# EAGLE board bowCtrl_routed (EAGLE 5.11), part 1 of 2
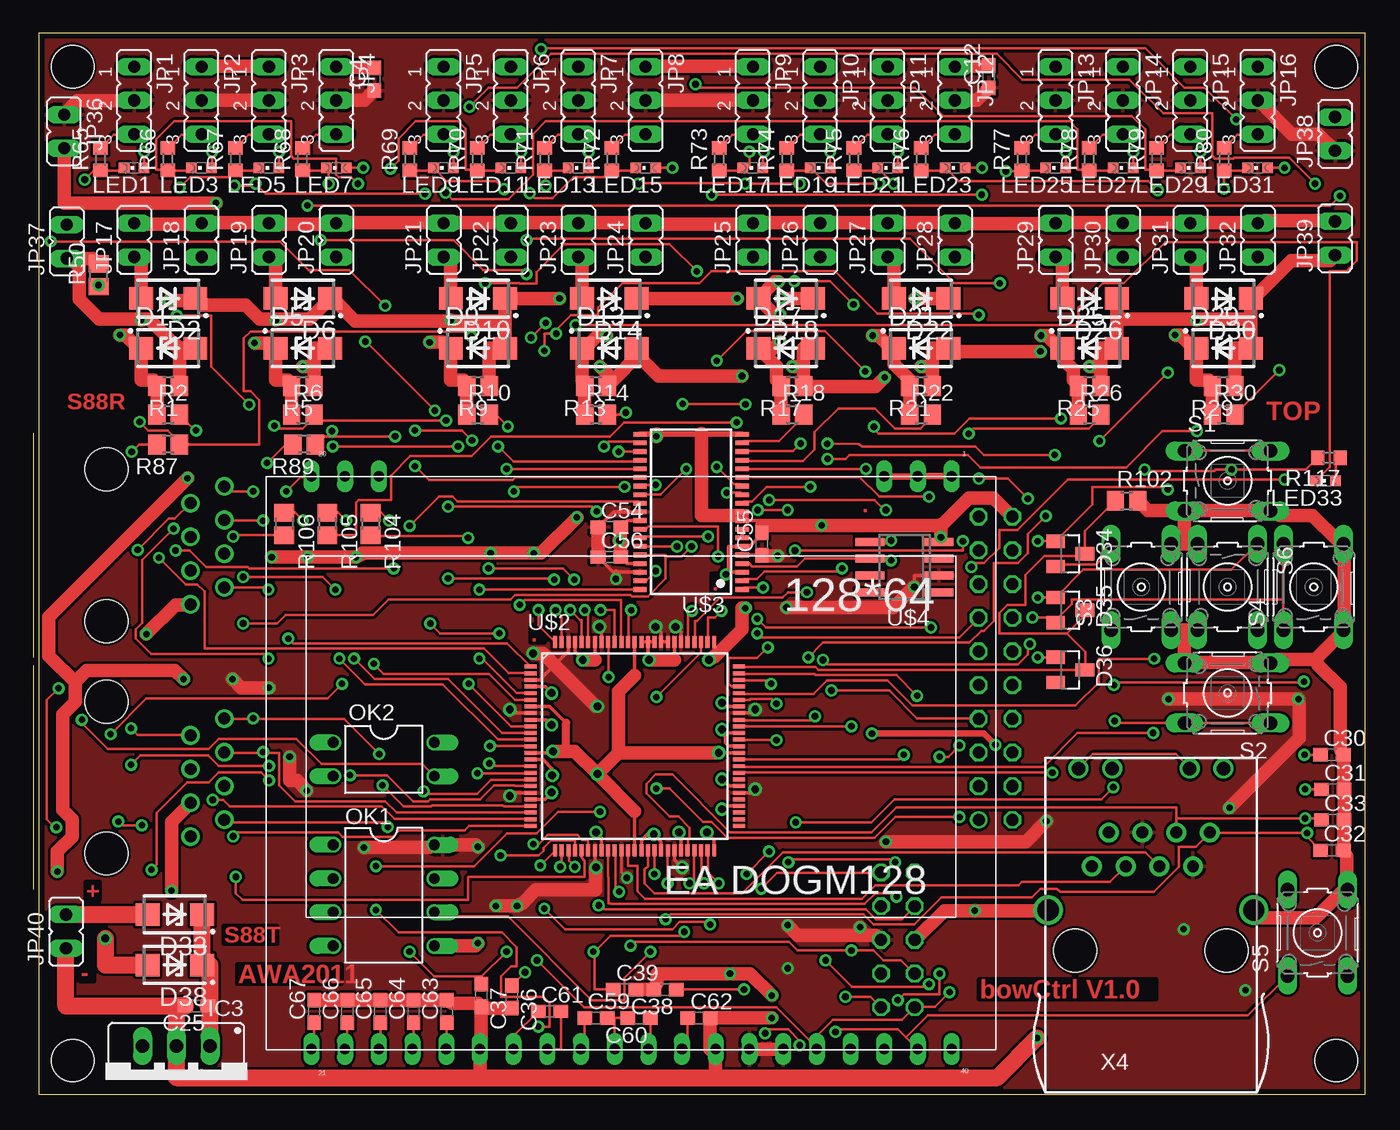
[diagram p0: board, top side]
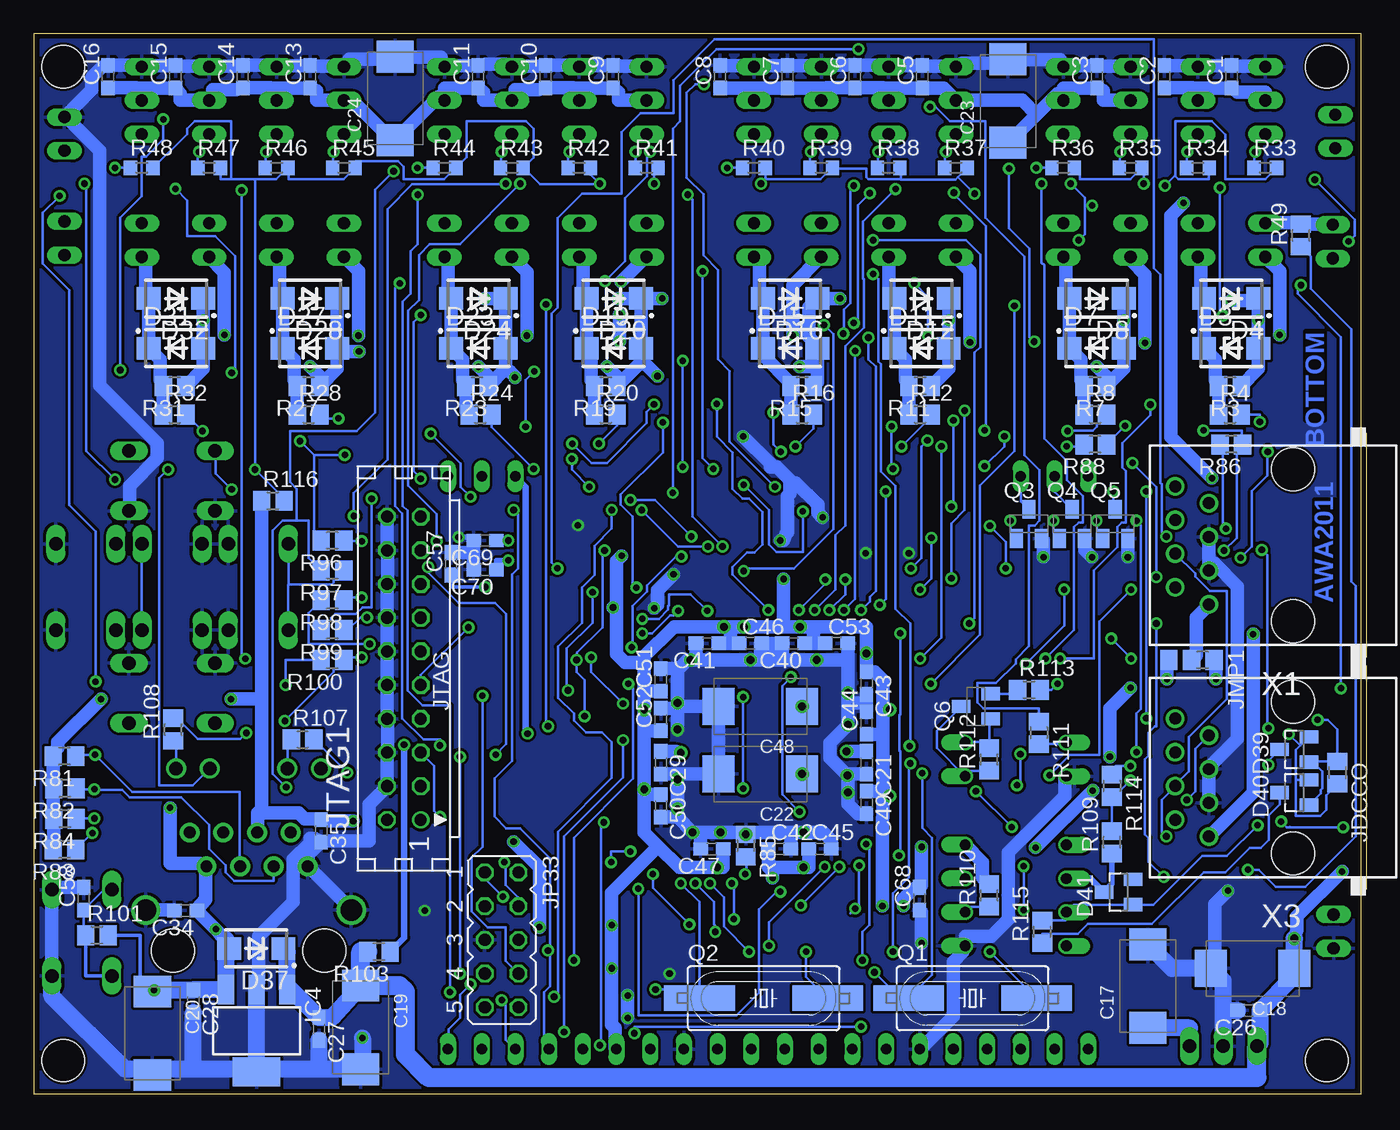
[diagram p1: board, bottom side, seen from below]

Size 100.43 x 80 mm. Coordinates in mm from the lower left corner, seen from the top.
Outline: 0.43,0 100.43,0 100.43,80 0.43,80 0.43,0
Copper layers (1*16): Top 0.035mm / dielectric 1.5mm / Bottom 0.035mm
Design rules "ZWILLING *": minimum track width 0.2mm, minimum drill 0.5mm, track to track 0.2mm, track to pad 0.2mm, pad to pad 0.15mm, via to via 0.2mm, smd to smd 0mil, copper to edge 0.2mm, drill to drill 0.2mm, minimum pad ring 0.2mm, minimum via ring 0.2mm, stop-mask expansion 0.1mm, vias tented up to drill 0mil, thermal gap 10mil
Net classes: 1 power: width 1 mm; 2 dcc: width 1 mm; 3 bled: width 0.5 mm
Holes 3.2 mm at 2.97,77.47 98.22,77.47 2.97,2.54 98.22,2.54

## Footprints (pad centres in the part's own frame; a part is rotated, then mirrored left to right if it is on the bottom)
C0603 = smd 1.1 x 1: 1 -0.85,0; 2 0.85,0
SMC_E = smd 2.4 x 2.8: + -3.15,0; - 3.15,0
DO214AC_ZENER = smd 1.8 x 1.7: A 2.05,0; C -2.05,0
SOT23 = smd 1 x 1.4: 1 -0.95,-1.1; 2 0.95,-1.1; 3 0,1.1
78XXS = drill 1.016 long: GND 0,-2.54; IN -2.54,-2.54; OUT 2.54,-2.54
SOT223 = smd 1.219 x 2.235: 1 -2.311,-3.099; 2 0,-3.099; 3 2.311,-3.099 | smd 3.6 x 2.2: 4 0,3.099
R0805 = smd 1.3 x 1.5: 1 -0.85,0; 2 0.85,0
A0R-JMP = smd 1.5 x 1.3: 1 0,1.7; 2 0,0; 3 0,-1.7
JP2 = drill 0.914 long: 1 -2.54,0; 2 0,0; 3 2.54,0
JP1 = drill 0.914 long: 1 0,-1.27; 2 0,1.27
JP5Q = drill 0.914 octagon: 1 -5.08,-1.27; 2 -5.08,1.27; 3 -2.54,-1.27; 4 -2.54,1.27; 5 0,-1.27; 6 0,1.27; 7 2.54,-1.27; 8 2.54,1.27; 9 5.08,-1.27; 10 5.08,1.27
JTAG-ARM = drill 0.914 round: 1 -11.43,-1.27 | drill 0.914 octagon: 2 -11.43,1.27; 3 -8.89,-1.27; 4 -8.89,1.27; 5 -6.35,-1.27; 6 -6.35,1.27; 7 -3.81,-1.27; 8 -3.81,1.27; 9 -1.27,-1.27; 10 -1.27,1.27; 11 1.27,-1.27; 12 1.27,1.27; 13 3.81,-1.27; 14 3.81,1.27; 15 6.35,-1.27; 16 6.35,1.27; 17 8.89,-1.27; 18 8.89,1.27; 19 11.43,-1.27; 20 11.43,1.27
CHIPLED_0603 = smd 0.8 x 0.8: A 0,-0.75; C 0,0.75
DIL08 = drill 0.813 offset: 1 -3.81,-3.81; 2 -1.27,-3.81; 3 1.27,-3.81; 4 3.81,-3.81; 5 3.81,3.81; 6 1.27,3.81; 7 -1.27,3.81; 8 -3.81,3.81
DIL04 = drill 0.813 offset: 1 -1.27,-3.81; 2 1.27,-3.81; 3 1.27,3.81; 4 -1.27,3.81
HC49UP = smd 5.334 x 1.93: 1 -4.826,0; 2 4.826,0
SOT23-BEC = smd 1 x 1.4: B -0.95,-1.1; C 0,1.1; E 0.95,-1.1
R0603 = smd 1 x 1.1: 1 -0.85,0; 2 0.85,0
B3F-10XX = drill 1.016 long: 1 -3.251,2.261; 2 3.251,2.261; 3 -3.251,-2.261; 4 3.251,-2.261
E_DOG-M_DISPLAY = drill 0.8 long: 1 0.032,0; 2 2.572,0; 3 5.112,0; 18 43.212,0; 19 45.752,0; 20 48.292,0; 21 48.292,43.18; 22 45.752,43.18; 23 43.212,43.18; 24 40.672,43.18; 25 38.132,43.18; 26 35.592,43.18; 27 33.052,43.18; 28 30.512,43.18; 29 27.972,43.18; 30 25.432,43.18; 31 22.892,43.18; 32 20.352,43.18; 33 17.812,43.18; 34 15.272,43.18; 35 12.732,43.18; 36 10.192,43.18; 37 7.652,43.18; 38 5.112,43.18; 39 2.572,43.18; 40 0.032,43.18
TQFP100 = smd 0.9 x 0.3: 1 -7.85,6; 2 -7.85,5.5; 3 -7.85,5; 4 -7.85,4.5; 5 -7.85,4; 6 -7.85,3.5; 7 -7.85,3; 8 -7.85,2.5; 9 -7.85,2; 10 -7.85,1.5; 11 -7.85,1; 12 -7.85,0.5; 13 -7.85,0; 14 -7.85,-0.5; 15 -7.85,-1; 16 -7.85,-1.5; 17 -7.85,-2; 18 -7.85,-2.5; 19 -7.85,-3; 20 -7.85,-3.5; 21 -7.85,-4; 22 -7.85,-4.5; 23 -7.85,-5; 24 -7.85,-5.5; 25 -7.85,-6; 51 7.85,-6; 52 7.85,-5.5; 53 7.85,-5; 54 7.85,-4.5; 55 7.85,-4; 56 7.85,-3.5; 57 7.85,-3; 58 7.85,-2.5; 59 7.85,-2; 60 7.85,-1.5; 61 7.85,-1; 62 7.85,-0.5; 63 7.85,0; 64 7.85,0.5; 65 7.85,1; 66 7.85,1.5; 67 7.85,2; 68 7.85,2.5; 69 7.85,3; 70 7.85,3.5; 71 7.85,4; 72 7.85,4.5; 73 7.85,5; 74 7.85,5.5; 75 7.85,6 | smd 0.3 x 0.9: 26 -6,-7.85; 27 -5.5,-7.85; 28 -5,-7.85; 29 -4.5,-7.85; 30 -4,-7.85; 31 -3.5,-7.85; 32 -3,-7.85; 33 -2.5,-7.85; 34 -2,-7.85; 35 -1.5,-7.85; 36 -1,-7.85; 37 -0.5,-7.85; 38 0,-7.85; 39 0.5,-7.85; 40 1,-7.85; 41 1.5,-7.85; 42 2,-7.85; 43 2.5,-7.85; 44 3,-7.85; 45 3.5,-7.85; 46 4,-7.85; 47 4.5,-7.85; 48 5,-7.85; 49 5.5,-7.85; 50 6,-7.85; 76 6,7.85; 77 5.5,7.85; 78 5,7.85; 79 4.5,7.85; 80 4,7.85; 81 3.5,7.85; 82 3,7.85; 83 2.5,7.85; 84 2,7.85; 85 1.5,7.85; 86 1,7.85; 87 0.5,7.85; 88 0,7.85; 89 -0.5,7.85; 90 -1,7.85; 91 -1.5,7.85; 92 -2,7.85; 93 -2.5,7.85; 94 -3,7.85; 95 -3.5,7.85; 96 -4,7.85; 97 -4.5,7.85; 98 -5,7.85; 99 -5.5,7.85; 100 -6,7.85
TSSOP38_R-PDSO-G38-DA = smd 0.35 x 1: 1 -5.85,-3.85; 2 -5.2,-3.85; 3 -4.55,-3.85; 4 -3.9,-3.85; 5 -3.25,-3.85; 6 -2.6,-3.85; 7 -1.95,-3.85; 8 -1.3,-3.85; 9 -0.65,-3.85; 10 0,-3.85; 11 0.65,-3.85; 12 1.3,-3.85; 13 1.95,-3.85; 14 2.6,-3.85; 15 3.25,-3.85; 16 3.9,-3.85; 17 4.55,-3.85; 18 5.2,-3.85; 19 5.85,-3.85; 20 5.85,3.85; 21 5.2,3.85; 22 4.55,3.85; 23 3.9,3.85; 24 3.25,3.85; 25 2.6,3.85; 26 1.95,3.85; 27 1.3,3.85; 28 0.65,3.85; 29 0,3.85; 30 -0.65,3.85; 31 -1.3,3.85; 32 -1.95,3.85; 33 -2.6,3.85; 34 -3.25,3.85; 35 -3.9,3.85; 36 -4.55,3.85; 37 -5.2,3.85; 38 -5.85,3.85
SO-08 = smd 0.6 x 2.2: 1 -1.905,-2.6; 2 -0.635,-2.6; 3 0.635,-2.6; 4 1.905,-2.6; 5 1.905,2.6; 6 0.635,2.6; 7 -0.635,2.6; 8 -1.905,2.6
RJ45-NO-SHIELD = drill 0.9 pad 1.4 round: 1 -4.445,6.35; 2 -3.175,8.89; 3 -1.905,6.35; 4 -0.635,8.89; 5 0.635,6.35; 6 1.905,8.89; 7 3.175,6.35; 8 4.445,8.89 | hole 3.251: -5.715,0; 5.715,0
SI-50170 = drill 0.9 pad 1.5 round: 1 4.445,5.842; 2 3.175,3.302; 3 1.905,5.842; 4 0.635,3.302; 5 -0.635,5.842; 6 -1.905,3.302; 7 -3.175,5.842; 8 -4.445,3.302 | drill 1.016 pad 1.5 round: A1 -5.461,10.668; A2 2.921,10.668; C1 -2.921,10.668; C2 5.461,10.668 | drill 1.6 pad 2.2 round: S1 -7.747,0; S2 7.747,0 | hole 3.251: -5.715,-3.048; 5.715,-3.048

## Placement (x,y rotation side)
C1  100n  [C0603]  10.15,76.72 90 bottom
C2  100n  [C0603]  15.23,76.72 90 bottom
C3  100n  [C0603]  20.31,76.72 90 bottom
C4  100n  [C0603]  25.72,76.53 90 top
C5  100n  [C0603]  33.47,76.72 90 bottom
C6  100n  [C0603]  38.55,76.72 90 bottom
C7  100n  [C0603]  43.63,76.72 90 bottom
C8  100n  [C0603]  48.71,76.72 90 bottom
C9  100n  [C0603]  56.79,76.72 90 bottom
C10  100n  [C0603]  61.87,76.72 90 bottom
C11  100n  [C0603]  66.95,76.72 90 bottom
C12  100n  [C0603]  72.03,76.72 90 top
C13  100n  [C0603]  79.61,76.72 90 bottom
C14  100n  [C0603]  84.69,76.72 90 bottom
C15  100n  [C0603]  89.77,76.72 90 bottom
C16  100n  [C0603]  94.85,76.72 90 bottom
C17  100µF  [SMC_E]  16.47,8.16 90 bottom
C18  100µF  [SMC_E]  8.57,9.49 180 bottom
C19  100µF  [SMC_E]  75.81,5.04 270 bottom
C20  100µF  [SMC_E]  91.51,4.6 270 bottom
C21  100n  [C0603]  37.68,25 270 bottom
C22  100µF  [SMC_E]  45.68,24.14 180 bottom
C23  100µF  [SMC_E]  27.01,74.88 90 bottom
C24  100µF  [SMC_E]  73.2,75.08 90 bottom
C25  100n  [C0603]  12.31,6.67 180 top
C26  100n  [C0603]  8.86,6.33 180 bottom
C27  100n  [C0603]  78.94,4.92 270 bottom
C28  100n  [C0603]  88.42,7 270 bottom
C29  10n  [C0603]  53.18,25 270 bottom
C30  10pF  [C0603]  97.91,25.6 0 top
C31  10pF  [C0603]  97.96,22.98 0 top
C32  10pF  [C0603]  97.91,18.39 0 top
C33  10pF  [C0603]  97.96,20.69 0 top
C34  100n  [C0603]  89.01,13.86 180 bottom
C35  100n  [C0603]  78.79,19.87 270 bottom
C36  18pF  [C0603]  36.08,7.35 270 top
C37  18pF  [C0603]  33.78,7.45 270 top
C38  18pF  [C0603]  47.63,7.9 180 top
C39  18pF  [C0603]  44.58,7.9 0 top
C40  100n  [C0603]  43.18,34 180 bottom
C41  100n  [C0603]  49.68,34 180 bottom
C42  100n  [C0603]  44.23,18.5 0 bottom
C43  100n  [C0603]  37.68,31 270 bottom
C44  100n  [C0603]  37.68,28 90 bottom
C45  100n  [C0603]  41.18,18.5 0 bottom
C46  100n  [C0603]  46.43,34 0 bottom
C47  100n  [C0603]  49.33,18.5 180 bottom
C48  100µF  [SMC_E]  45.68,29.25 180 bottom
C49  100n  [C0603]  37.68,22 270 bottom
C50  100n  [C0603]  53.18,21.75 270 bottom
C51  100n  [C0603]  53.18,31.25 90 bottom
C52  100n  [C0603]  53.18,28.25 90 bottom
C53  100n  [C0603]  39.93,34 0 bottom
C54  100n  [C0603]  43.43,42.75 0 top
C55  100n  [C0603]  54.93,41.5 90 top
C56  100n  [C0603]  43.43,40.5 0 top
C57  1µF  [C0603]  68.98,40 90 bottom
C58  100n  [C0603]  96.68,14.75 90 bottom
C59  1µF  [C0603]  42.43,5.75 0 top
C60  1µF  [C0603]  45.68,5.75 180 top
C61  1µF  [C0603]  38.93,6.25 0 top
C62  1µF  [C0603]  50.18,5.75 0 top
C63  1µF  [C0603]  31.18,6.25 90 top
C64  1µF  [C0603]  28.68,6.25 90 top
C65  1µF  [C0603]  26.18,6.25 90 top
C66  1µF  [C0603]  23.68,6.25 90 top
C67  1µF  [C0603]  21.18,6.25 90 top
C68  100n  [C0603]  33.68,14.75 90 bottom
C69  1µF  [C0603]  66.43,41.75 180 bottom
C70  1µF  [C0603]  66.43,39.55 180 bottom
D1  SMAJ5.0A  [DO214AC_ZENER]  10.18,56.25 0 top
D2  SMAJ5.0A  [DO214AC_ZENER]  10.18,60 180 top
D3  SMAJ5.0A  [DO214AC_ZENER]  10.18,56.25 0 bottom
D4  SMAJ5.0A  [DO214AC_ZENER]  10.18,60 180 bottom
D5  SMAJ5.0A  [DO214AC_ZENER]  20.33,56.25 0 top
D6  SMAJ5.0A  [DO214AC_ZENER]  20.33,60 180 top
D7  SMAJ5.0A  [DO214AC_ZENER]  20.33,56.25 0 bottom
D8  SMAJ5.0A  [DO214AC_ZENER]  20.33,60 180 bottom
D9  SMAJ5.0A  [DO214AC_ZENER]  33.53,56.25 0 top
D10  SMAJ5.0A  [DO214AC_ZENER]  33.53,60 180 top
D11  SMAJ5.0A  [DO214AC_ZENER]  33.53,56.25 0 bottom
D12  SMAJ5.0A  [DO214AC_ZENER]  33.53,60 180 bottom
D13  SMAJ5.0A  [DO214AC_ZENER]  43.43,56.25 0 top
D14  SMAJ5.0A  [DO214AC_ZENER]  43.43,60 180 top
D15  SMAJ5.0A  [DO214AC_ZENER]  43.43,56.25 0 bottom
D16  SMAJ5.0A  [DO214AC_ZENER]  43.43,60 180 bottom
D17  SMAJ5.0A  [DO214AC_ZENER]  56.73,56.25 0 top
D18  SMAJ5.0A  [DO214AC_ZENER]  56.73,60 180 top
D19  SMAJ5.0A  [DO214AC_ZENER]  56.73,56.25 0 bottom
D20  SMAJ5.0A  [DO214AC_ZENER]  56.73,60 180 bottom
D21  SMAJ5.0A  [DO214AC_ZENER]  66.93,56.25 0 top
D22  SMAJ5.0A  [DO214AC_ZENER]  66.93,60 180 top
D23  SMAJ5.0A  [DO214AC_ZENER]  66.93,56.25 0 bottom
D24  SMAJ5.0A  [DO214AC_ZENER]  66.93,60 180 bottom
D25  SMAJ5.0A  [DO214AC_ZENER]  79.63,56.25 0 top
D26  SMAJ5.0A  [DO214AC_ZENER]  79.63,60 180 top
D27  SMAJ5.0A  [DO214AC_ZENER]  79.63,56.25 0 bottom
D28  SMAJ5.0A  [DO214AC_ZENER]  79.63,60 180 bottom
D29  SMAJ5.0A  [DO214AC_ZENER]  89.73,56.25 0 top
D30  SMAJ5.0A  [DO214AC_ZENER]  89.73,60 180 top
D31  SMAJ5.0A  [DO214AC_ZENER]  89.73,56.25 0 bottom
D32  SMAJ5.0A  [DO214AC_ZENER]  89.73,60 180 bottom
D33  SMAJ5.0A  [DO214AC_ZENER]  10.68,13.56 180 top
D34  BAS40-05  [SOT23]  78.18,40.75 270 top
D35  BAS40-05  [SOT23]  78.18,36.5 270 top
D36  BAS40-05  [SOT23]  78.18,32 270 top
D37  SMAJ5.0A  [DO214AC_ZENER]  83.68,11 180 bottom
D38  SMAJ5.0A  [DO214AC_ZENER]  10.68,9.75 180 top
D39  BAV199  [SOT23]  5.43,26 90 bottom
D40  BAV199  [SOT23]  5.43,22.75 90 bottom
D41  BAV199  [SOT23]  18.68,15.25 90 bottom
IC3  7805  [78XXS]  10.79,1.09 180 top
IC4  LM  [SOT223]  83.66,4.79 180 bottom
JDCCO  ?  [R0805]  2.18,24.25 270 bottom
JMP1  0R-JUMPA  [A0R-JMP]  13.18,32.75 270 bottom
JP1  [JP2]  7.61,74.93 270 top
JP2  [JP2]  12.69,74.93 270 top
JP3  [JP2]  17.77,74.93 270 top
JP4  [JP2]  22.85,74.93 270 top
JP5  [JP2]  30.93,74.93 270 top
JP6  [JP2]  36.01,74.93 270 top
JP7  [JP2]  41.09,74.93 270 top
JP8  [JP2]  46.17,74.93 270 top
JP9  [JP2]  54.25,74.93 270 top
JP10  [JP2]  59.33,74.93 270 top
JP11  [JP2]  64.41,74.93 270 top
JP12  [JP2]  69.49,74.93 270 top
JP13  [JP2]  77.07,74.93 270 top
JP14  [JP2]  82.15,74.93 270 top
JP15  [JP2]  87.23,74.93 270 top
JP16  [JP2]  92.31,74.93 270 top
JP17  [JP1]  7.61,64.4 0 top
JP18  [JP1]  12.69,64.4 0 top
JP19  [JP1]  17.77,64.4 0 top
JP20  [JP1]  22.85,64.4 0 top
JP21  [JP1]  30.93,64.4 0 top
JP22  [JP1]  36.01,64.4 0 top
JP23  [JP1]  41.09,64.4 0 top
JP24  [JP1]  46.17,64.4 0 top
JP25  [JP1]  54.25,64.4 0 top
JP26  [JP1]  59.33,64.4 0 top
JP27  [JP1]  64.41,64.4 0 top
JP28  [JP1]  69.49,64.4 0 top
JP29  [JP1]  77.07,64.4 0 top
JP30  [JP1]  82.15,64.4 0 top
JP31  [JP1]  87.23,64.4 0 top
JP32  [JP1]  92.31,64.4 0 top
JP33  [JP5Q]  65.18,11.64 270 bottom
JP36  [JP1]  2.33,72.59 180 top
JP37  [JP1]  2.53,64.29 0 top
JP38  [JP1]  98.14,72.41 0 top
JP39  [JP1]  98.14,64.54 0 top
JP40  [JP1]  2.47,12.28 0 top
JTAG1  JTAG-ARM  [JTAG-ARM]  72.55,32.12 90 bottom
LED1  [CHIPLED_0603]  7.61,69.85 90 top
LED3  [CHIPLED_0603]  12.69,69.85 90 top
LED5  [CHIPLED_0603]  17.77,69.85 90 top
LED7  [CHIPLED_0603]  22.85,69.85 90 top
LED9  [CHIPLED_0603]  30.93,69.85 90 top
LED11  [CHIPLED_0603]  36.01,69.85 90 top
LED13  [CHIPLED_0603]  41.09,69.85 90 top
LED15  [CHIPLED_0603]  46.17,69.85 90 top
LED17  [CHIPLED_0603]  54.25,69.85 90 top
LED19  [CHIPLED_0603]  59.33,69.85 90 top
LED21  [CHIPLED_0603]  64.41,69.85 90 top
LED23  [CHIPLED_0603]  69.49,69.85 90 top
LED25  [CHIPLED_0603]  77.07,69.85 90 top
LED27  [CHIPLED_0603]  82.15,69.85 90 top
LED29  [CHIPLED_0603]  87.23,69.85 90 top
LED31  [CHIPLED_0603]  92.31,69.85 90 top
LED33  [CHIPLED_0603]  97.43,46.25 90 top
OK1  6N137  [DIL08]  26.43,15 270 top
OK2  PC817  [DIL04]  26.43,25.25 270 top
Q1  25MHz  [HC49UP]  29.68,7.25 0 bottom
Q2  8MHz  [HC49UP]  45.43,7.25 0 bottom
Q3  BCF81SMD  [SOT23-BEC]  25.43,43 0 bottom
Q4  BCF81SMD  [SOT23-BEC]  22.18,43 0 bottom
Q5  BCF81SMD  [SOT23-BEC]  18.93,43 0 bottom
Q6  BC857BSMD  [SOT23-BEC]  29.43,29.25 90 bottom
R1  22  [R0805]  10.18,53.4 180 top
R2  1k  [R0805]  10.18,51.25 0 top
R3  22  [R0805]  10.28,53.4 180 bottom
R4  1k  [R0805]  10.28,51.25 0 bottom
R5  22  [R0805]  20.33,53.4 180 top
R6  1k  [R0805]  20.33,51.25 0 top
R7  22  [R0805]  20.43,53.4 180 bottom
R8  1k  [R0805]  20.43,51.25 0 bottom
R9  22  [R0805]  33.53,53.4 180 top
R10  1k  [R0805]  33.53,51.25 0 top
R11  22  [R0805]  33.63,53.4 180 bottom
R12  1k  [R0805]  33.63,51.25 0 bottom
R13  22  [R0805]  42.43,53.4 180 top
R14  1k  [R0805]  42.43,51.25 0 top
R15  22  [R0805]  42.53,53.4 180 bottom
R16  1k  [R0805]  42.53,51.25 0 bottom
R17  22  [R0805]  57.23,53.4 180 top
R18  1k  [R0805]  57.23,51.25 0 top
R19  22  [R0805]  57.33,53.4 180 bottom
R20  1k  [R0805]  57.33,51.25 0 bottom
R21  22  [R0805]  66.93,53.4 180 top
R22  1k  [R0805]  66.93,51.25 0 top
R23  22  [R0805]  67.03,53.4 180 bottom
R24  1k  [R0805]  66.78,51.25 0 bottom
R25  22  [R0805]  79.63,53.4 180 top
R26  1k  [R0805]  79.63,51.25 0 top
R27  22  [R0805]  79.73,53.4 180 bottom
R28  1k  [R0805]  79.73,51.25 0 bottom
R29  22  [R0805]  89.73,53.4 180 top
R30  1k  [R0805]  89.73,51.25 0 top
R31  22  [R0805]  89.83,53.4 180 bottom
R32  1k  [R0805]  89.83,51.25 0 bottom
R33  220  [R0603]  7.61,69.85 0 bottom
R34  220  [R0603]  12.69,69.85 0 bottom
R35  220  [R0603]  17.77,69.85 0 bottom
R36  220  [R0603]  22.85,69.85 0 bottom
R37  220  [R0603]  30.93,69.85 0 bottom
R38  220  [R0603]  36.01,69.85 0 bottom
R39  220  [R0603]  41.09,69.85 0 bottom
R40  220  [R0603]  46.17,69.85 0 bottom
R41  220  [R0603]  54.25,69.85 0 bottom
R42  220  [R0603]  59.33,69.85 0 bottom
R43  220  [R0603]  64.41,69.85 0 bottom
R44  220  [R0603]  69.49,69.85 0 bottom
R45  220  [R0603]  77.07,69.85 0 bottom
R46  220  [R0603]  82.15,69.85 0 bottom
R47  220  [R0603]  87.23,69.85 0 bottom
R48  220  [R0603]  92.31,69.85 0 bottom
R49  0R  [R0805]  4.93,64.75 90 bottom
R50  0R  [R0805]  4.93,61.75 90 top
R65  220  [R0603]  5.07,70.5 90 top
R66  220  [R0603]  10.15,70.5 90 top
R67  220  [R0603]  15.23,70.5 90 top
R68  220  [R0603]  20.31,70.5 90 top
R69  220  [R0603]  28.39,70.5 90 top
R70  220  [R0603]  33.47,70.5 90 top
R71  220  [R0603]  38.55,70.5 90 top
R72  220  [R0603]  43.63,70.5 90 top
R73  220  [R0603]  51.71,70.5 90 top
R74  220  [R0603]  56.79,70.5 90 top
R75  220  [R0603]  61.87,70.5 90 top
R76  220  [R0603]  66.95,70.5 90 top
R77  220  [R0603]  74.53,70.5 90 top
R78  220  [R0603]  79.61,70.5 90 top
R79  220  [R0603]  84.69,70.5 90 top
R80  220  [R0603]  89.77,70.5 90 top
R81  49.9  [R0805]  98.13,25.49 180 bottom
R82  49.9  [R0805]  98.11,23.05 180 bottom
R83  49.9  [R0805]  98.13,18.45 180 bottom
R84  49.9  [R0805]  98.11,20.76 180 bottom
R85  12.4k  [R0805]  46.78,18.75 270 bottom
R86  0R  [R0805]  10.18,49 180 bottom
R87  0R  [R0805]  10.18,49 180 top
R88  0R  [R0805]  20.43,49 180 bottom
R89  0R  [R0805]  20.43,49 180 top
R96  10k  [R0805]  77.93,41.75 180 bottom
R97  10k  [R0805]  77.93,39.5 180 bottom
R98  10k  [R0805]  77.93,37.25 180 bottom
R99  10k  [R0805]  77.93,35 180 bottom
R100  10k  [R0805]  77.93,32.75 180 bottom
R101  10k  [R0805]  95.68,12 0 bottom
R102  100k  [R0805]  82.43,44.75 0 top
R103  100  [R0805]  74.43,10.75 180 bottom
R104  1k  [R0805]  25.43,43 270 top
R105  1k  [R0805]  22.18,43 270 top
R106  1k  [R0805]  18.93,43 270 top
R107  330  [R0805]  80.18,26.75 0 bottom
R108  330  [R0805]  89.93,27.5 90 bottom
R109  1.5k  [R0805]  19.18,19 90 bottom
R110  10k  [R0805]  28.43,15 90 bottom
R111  1k  [R0805]  24.68,27.25 270 bottom
R112  ?  [R0805]  28.43,25.25 90 bottom
R113  100  [R0805]  25.43,30.5 0 bottom
R114  0R  [R0805]  19.18,23.25 270 bottom
R115  0R  [R0805]  24.43,12.25 90 bottom
R116  0R  [R0805]  82.43,44.75 0 bottom
R117  220  [R0603]  97.68,48 180 top
S1  [B3F-10XX]  90.03,46.25 0 top
S2  [B3F-10XX]  90.03,30.25 180 top
S3  [B3F-10XX]  83.53,38.25 90 top
S4  [B3F-10XX]  96.53,38.25 90 top
S5  [B3F-10XX]  96.82,12.18 90 top
S6  [B3F-10XX]  90.03,38.25 270 top
U$1  [E_DOG-M_DISPLAY]  69.26,46.58 180 top
U$2  LM3S6965_TQFP100  [TQFP100]  45.34,26.24 0 top
U$3  ADS7953  [TSSOP38_R-PDSO-G38-DA]  49.59,43.91 90 top
U$4  REF5025  [SO-08]  65.68,39.75 90 top
X1  RJ45-6L-B  [RJ45-NO-SHIELD]  5.51,41.39 90 bottom
X3  RJ45-6L-B  [RJ45-NO-SHIELD]  5.51,23.88 90 bottom
X4  SI-50170  [SI-50170]  84.26,13.89 0 top

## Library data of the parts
C1-C70 = rcl
D1-D33 D37 D38 = SMAJ_suppressors_CA_A
D34-D36 D39-D41 = diode
IC3 = v-reg
IC4 = linear-technology; MPN: LT1129CST-5#PBF; OC_FARNELL: 1663375; OC_NEWARK: 57M2069
JDCCO R1-R50 R65-R89 R96-R117 = resistor
JMP1 = jump-0r-smd
JP1-JP33 JP36-JP40 = jumper
JTAG1 = nxp
LED1 LED3 LED5 LED7 LED9 LED11 LED13 LED15 LED17 LED19 LED21 LED23 LED25 LED27 LED29 LED31 LED33 = led
OK1 = optocoupler; MPN: 6N137; OC_FARNELL: 1328376; OC_NEWARK: 52M1895
OK2 = optocoupler; MPN: PC817X4J000F; OC_FARNELL: 9707727; OC_NEWARK: 97K7059
Q1 Q2 = crystal; OC_FARNELL: unknown; OC_NEWARK: unknown
Q3-Q5 = transistor-npn
Q6 = transistor-pnp
S1-S6 = switch-omron
U$1 = display_ea_dogm128
U$2-U$4 = texas_lumi
X1 X3 = con-tycoelectronics
X4 = con-stewart; OC_FARNELL: unknown; OC_NEWARK: unknown

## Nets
ADCIO0: LED33.C U$3.37
ADCIO1: R104.2 U$3.38
ADCIO2: R105.2 U$3.1
ADCIO3: R106.2 U$3.2
BLED [bled]: R103.1 U$1.1 U$1.2 U$1.3
DCC0 [dcc]: D1.C D2.A JP17.1 R1.2 R2.1
DCC1 [dcc]: D3.C D4.A JP18.1 R3.2 R4.1
DCC2 [dcc]: D5.C D6.A JP19.1 R5.2 R6.1
DCC3 [dcc]: D7.C D8.A JP20.1 R7.2 R8.1
DCC4 [dcc]: D9.C D10.A JP21.1 R9.2 R10.1
DCC5 [dcc]: D11.C D12.A JP22.1 R11.2 R12.1
DCC6 [dcc]: D13.C D14.A JP23.1 R13.2 R14.1
DCC7 [dcc]: D15.C D16.A JP24.1 R15.2 R16.1
DCC8 [dcc]: D17.C D18.A JP25.1 R17.2 R18.1
DCC9 [dcc]: D19.C D20.A JP26.1 R19.2 R20.1
DCC10 [dcc]: D21.C D22.A JP27.1 R21.2 R22.1
DCC11 [dcc]: D23.C D24.A JP28.1 R23.2 R24.1
DCC12 [dcc]: D25.C D26.A JP29.1 R25.2 R26.1
DCC13 [dcc]: D27.C D28.A JP30.1 R27.2 R28.1
DCC14 [dcc]: D29.C D30.A JP31.1 R29.2 R30.1
DCC15 [dcc]: D31.C D32.A JP32.1 R31.2 R32.1
DCC_OC_R: OK1.6 R110.1 U$2.47
DCC_OC_T: R111.1 U$2.61
DCCN [dcc]: D1.A D2.C D3.A D4.C D5.A D6.C D7.A D8.C D9.A D10.C D11.A D12.C D13.A D14.C D15.A D16.C D17.A D18.C D19.A D20.C D21.A D22.C D23.A D24.C D25.A D26.C D27.A D28.C D29.A D30.C D31.A D32.C JP37.1 JP39.1 R1.1 R3.1 R5.1 R7.1 R9.1 R11.1 R13.1 R15.1 R17.1 R19.1 R21.1 R23.1 R25.1 R27.1 R29.1 R31.1 R50.2
DCCP [dcc]: JP17.2 JP18.2 JP19.2 JP20.2 JP21.2 JP22.2 JP23.2 JP24.2 JP25.2 JP26.2 JP27.2 JP28.2 JP29.2 JP30.2 JP31.2 JP32.2 JP37.2 JP39.2 R49.2
FTDI_RX: JP33.4 U$2.26
FTDI_TX: JP33.3 U$2.27
GND [power]: C1.2 C2.2 C3.2 C4.2 C5.2 C6.2 C7.2 C8.2 C9.2 C10.2 C11.2 C12.2 C13.2 C14.2 C15.2 C16.2 C17.- C18.- C19.- C20.- C21.2 C22.- C23.- C24.- C25.2 C26.2 C27.2 C28.2 C29.2 C30.2 C31.2 C32.2 C33.2 C34.2 C35.2 C36.2 C37.2 C38.2 C39.2 C40.2 C41.2 C42.2 C43.2 C44.2 C45.2 C46.2 C47.2 C48.- C49.2 C50.2 C51.2 C52.2 C53.2 C54.2 C55.2 C56.2 C57.2 C58.2 C62.2 C63.2 C64.2 C65.2 C66.2 C67.2 C68.1 C69.2 C70.2 IC3.GND IC4.2 IC4.4 JP1.1 JP2.1 JP3.1 JP4.1 JP5.1 JP6.1 JP7.1 JP8.1 JP9.1 JP10.1 JP11.1 JP12.1 JP13.1 JP14.1 JP15.1 JP16.1 JP33.5 JP38.2 JP40.1 JTAG1.4 JTAG1.6 JTAG1.8 JTAG1.10 JTAG1.12 JTAG1.14 JTAG1.16 JTAG1.18 JTAG1.20 OK1.5 OK2.2 Q3.E Q4.E Q5.E R85.1 R102.2 S1.3 S1.4 S2.3 S2.4 S3.3 S3.4 S4.3 S4.4 S5.3 S5.4 S6.3 S6.4 U$1.26 U$1.33 U$2.4 U$2.9 U$2.15 U$2.21 U$2.33 U$2.39 U$2.42 U$2.45 U$2.50 U$2.54 U$2.57 U$2.63 U$2.65 U$2.69 U$2.76 U$2.82 U$2.85 U$2.86 U$2.87 U$2.94 U$2.97 U$3.3 U$3.6 U$3.9 U$3.10 U$3.19 U$3.20 U$3.30 U$3.35 U$4.4 X1.3 X1.5 X3.3 X3.5 X4.8 X4.S1 X4.S2
I2C_SCL: JP33.1 U$2.34
I2C_SDA: JP33.2 U$2.35
KEY_RX: D34.3 D35.3 D36.3 R102.1 U$2.75
N$1: R85.2 U$2.41
N$2: U$3.7 U$3.8
N$3: R86.2 U$2.1
N$4: LED1.A R33.1
N$5: C59.2 C60.2 U$1.30
N$6: LED3.A R34.1
N$7: R87.2 U$2.2
N$8: LED5.A R35.1
N$9: R88.2 U$2.5
N$10: R89.2 U$2.6
N$11: LED33.A R117.1
N$12: JP1.3 R65.2
N$13: D34.1 R96.1 S1.1 S1.2
N$14: D34.2 R97.1 S3.1 S3.2
N$15: D35.1 R98.1 S6.1 S6.2
N$16: JP2.3 R66.2
N$17: C59.1 U$1.29
N$18: D35.2 R99.1 S4.1 S4.2
N$19: D36.1 R100.1 S2.1 S2.2
N$20: JP3.3 R67.2
N$21: C61.1 U$1.27
N$22: LED7.A R36.1
N$23: C61.2 U$1.28
N$24: C60.1 U$1.31
N$25: C62.1 U$1.32
N$26: JP4.3 R68.2
N$28: LED9.A R37.1
N$29: C63.1 U$1.25
N$30: C64.1 U$1.24
N$31: C65.1 U$1.23
N$32: JP5.3 R69.2
N$33: C66.1 U$1.22
N$34: LED11.A R38.1
N$35: C67.1 U$1.21
N$36: JP6.3 R70.2
N$37: LED13.A R39.1
N$38: C38.1 Q2.1 U$2.49
N$39: JP7.3 R71.2
N$40: LED15.A R40.1
N$41: C39.1 Q2.2 U$2.48
N$42: JP8.3 R72.2
N$43: LED17.A R41.1
N$44: Q3.B R104.1
N$45: JP9.3 R73.2
N$46: LED19.A R42.1
N$47: Q4.B R105.1
N$48: JP10.3 R74.2
N$49: LED21.A R43.1
N$50: Q5.B R106.1
N$51: JP11.3 R75.2
N$52: LED23.A R44.1
N$53: D41.1 OK1.3 R50.1 R115.2
N$54: JP12.3 R76.2
N$55: LED25.A R45.1
N$56: R49.1 R109.2 R114.2
N$57: JP13.3 R77.2
N$58: LED27.A R46.1
N$59: Q3.C U$1.18
N$60: JP14.3 R78.2
N$61: LED29.A R47.1
N$62: Q4.C U$1.19
N$63: JP15.3 R79.2
N$64: LED31.A R48.1
N$65: Q5.C U$1.20
N$66: JP16.3 R80.2
N$68: C69.1 U$4.5
N$69: C70.1 U$3.4 U$4.6
N$83: R107.1 X4.C1
N$84: R108.1 X4.C2
N$85: D41.3 OK1.2 R109.1
N$86: OK2.4 Q6.B R112.2
N$87: OK2.1 R111.2
N$88: D39.1 D40.1 JDCCO.1 OK2.3 Q6.C R112.1
N$89: Q6.E R113.1
N$90: D39.2 D40.2 JDCCO.2 R113.2
N$91: D40.3 R115.1
N$92: D39.3 R114.1
PHY_LED0: R107.2 U$2.59
PHY_LED1: R108.2 U$2.60
RST_N: C58.1 R101.1 S5.1 S5.2 U$1.39 U$2.64
RTCK: JTAG1.11
RXIN: C31.1 R82.1 U$2.37 X4.6
RXIP: C30.1 R81.1 U$2.40 X4.4
S88_5V [power]: JMP1.2 X1.1 X3.1
S88_CLK: U$2.25 X1.4 X3.4
S88_PS: U$2.23 X1.6 X3.6
S88_RAILD: U$2.22 X1.8 X3.8
S88_RST: U$2.24 X1.7 X3.7
S88_RX: U$2.19 X1.2
S88_TX: U$2.18 X3.2
SENSE0: R2.2 R86.1 U$3.28
SENSE1: R4.2 R87.1 U$3.27
SENSE2: R6.2 R88.1 U$3.26
SENSE3: R8.2 R89.1 U$3.25
SENSE4: R10.2 U$3.24
SENSE5: R12.2 U$3.23
SENSE6: R14.2 U$3.22
SENSE7: R16.2 U$3.21
SENSE8: R18.2 U$3.18
SENSE9: R20.2 U$3.17
SENSE10: R22.2 U$3.16
SENSE11: R24.2 U$3.15
SENSE12: R26.2 U$3.14
SENSE13: R28.2 U$3.13
SENSE14: R30.2 U$3.12
SENSE15: R32.2 U$3.11
SERV0: LED1.C R65.1 U$2.10
SERV1: LED3.C R66.1 U$2.11
SERV2: LED5.C R67.1 U$2.12
SERV3: LED7.C R68.1 R100.2 U$2.13
SERV4: LED9.C R69.1 U$2.95
SERV5: LED11.C R70.1 U$2.96
SERV6: LED13.C R71.1 R99.2 U$2.99
SERV7: LED15.C R72.1 U$2.100
SERV8: LED17.C R73.1 U$2.66
SERV9: LED19.C R74.1 R98.2 U$2.67
SERV10: LED21.C R75.1 U$2.70
SERV11: LED23.C R76.1 U$2.71
SERV12: LED25.C R77.1 R97.2 U$2.92
SERV13: LED27.C R78.1 U$2.91
SERV14: LED29.C R79.1 U$2.90
SERV15: LED31.C R80.1 R96.2 U$2.89
SPI_A0: U$1.38 U$2.29
SPI_CS_ADC: U$2.72 U$3.31
SPI_CS_DOGM: U$1.40 U$2.73
SPI_CS_SD: JP33.8 U$2.74
SPI_SCLK: JP33.7 U$1.37 U$2.28 U$3.32
SPI_SDI: JP33.9 U$1.36 U$2.31 U$3.33
SPI_SDO: JP33.10 U$2.30 U$3.34
TCK: JTAG1.9 U$2.80
TDI: JTAG1.5 U$2.78
TDO: JTAG1.13 U$2.77
TMS: JTAG1.7 U$2.79
TXON: C33.1 R84.1 U$2.46 X4.3
TXOP: C32.1 R83.1 U$2.43 X4.1
V2_5 [power]: C21.1 C22.+ C29.1 U$2.7 U$2.14 U$2.38 U$2.62 U$2.88
V3_3 [power]: C20.+ C28.1 C34.1 C35.1 C40.1 C41.1 C42.1 C43.1 C44.1 C45.1 C46.1 C47.1 C48.+ C49.1 C50.1 C51.1 C52.1 C53.1 C54.1 C55.1 C56.1 C57.1 C68.2 D37.A IC4.3 JMP1.3 JP33.6 OK1.8 R81.2 R82.2 R83.2 R84.2 R101.2 R110.2 R116.1 U$1.34 U$1.35 U$2.3 U$2.8 U$2.20 U$2.32 U$2.36 U$2.44 U$2.56 U$2.68 U$2.81 U$2.83 U$2.84 U$2.93 U$2.98 U$3.5 U$3.29 U$3.36 U$4.2 X4.2 X4.5
V5_0 [power]: C18.+ C19.+ C26.1 C27.1 D37.C D38.A IC3.OUT IC4.1 JMP1.1 JP36.2 R103.2
V5_0S [power]: C1.1 C2.1 C3.1 C4.1 C5.1 C6.1 C7.1 C8.1 C9.1 C10.1 C11.1 C12.1 C13.1 C14.1 C15.1 C16.1 C23.+ C24.+ JP1.2 JP2.2 JP3.2 JP4.2 JP5.2 JP6.2 JP7.2 JP8.2 JP9.2 JP10.2 JP11.2 JP12.2 JP13.2 JP14.2 JP15.2 JP16.2 JP36.1 JP38.1
VBAT: U$2.55
VIN [power]: D33.A JP40.2
VING [power]: C17.+ C25.1 D33.C D38.C IC3.IN
VLEDL: R33.2 R34.2 R35.2 R36.2 R37.2 R38.2 R39.2 R40.2 R41.2 R42.2 R43.2 R44.2 R45.2 R46.2 R47.2 R48.2 R116.2 R117.2 X4.A1 X4.A2
XTAL1: C37.1 Q1.2 U$2.16
XTAL2: C36.1 Q1.1 U$2.17

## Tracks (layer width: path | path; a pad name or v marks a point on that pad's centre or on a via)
ADCIO0  (via drill 0.5)
  Top 0.2: LED33.C 97.73,47.3 97.73,62.05 98.98,62.05 99.78,62.85 99.78,64.25 85.33,64.25 82.23,61.15 80.63,61.15 78.78,59.3 78.78,58 v40.88,58 | v46.93,39.45 46.23,38.75 45.78,38.75 U$3.37
  Bottom 0.2: v40.88,58 40.18,57.3 40.18,42.6 43.13,39.65 46.93,39.65 v46.93,39.45
ADCIO1  (via drill 0.5)
  Top 0.2: v33.63,38.05 U$3.38 | v32.78,41.95 32.63,42.1 25.48,42.1 R104.2
  Bottom 0.2: v33.63,38.05 32.78,38.9 v32.78,41.95
ADCIO2  (via drill 0.5)
  Top 0.2: v55.03,38.2 53.58,38.2 U$3.1 | v53.03,50.65 44.53,50.65 43.48,49.6 34.53,49.6 33.03,48.1 28.43,48.1 26.98,46.65 26.98,44.8 24.53,44.8 24.33,44.6 24.33,42.15 R105.2
  Bottom 0.2: v55.03,38.2 55.33,38.5 55.33,43.55 56.23,44.45 56.23,45.2 53.03,48.4 v53.03,50.65
ADCIO3  (via drill 0.5)
  Top 0.2: v60.98,39.65 60.73,39.4 55.13,39.4 54.58,38.85 53.58,38.85 U$3.2 | v15.08,42.05 15.18,42.15 R106.2
  Bottom 0.2: v60.98,39.65 61.43,40.1 61.43,58.85 60.98,59.3 60.98,66.05 59.13,67.9 56.13,67.9 56.13,72.55 54.73,73.95 52.23,73.95 52.23,76.45 49.13,79.55 16.03,79.55 16.03,62.3 15.53,61.8 15.53,46.1 15.43,46 15.43,42.4 v15.08,42.05
BLED  (via drill 0.5)
  Top 0.5: v72.53,26.35 71.68,27.2 v63.23,27.2 | U$1.1 69.18,46.6 66.73,46.6 U$1.2 U$1.3
  Bottom 0.5: R103.1 72.53,11.8 v72.53,26.35 | v63.23,27.2 63.38,27.35 63.38,45.8 64.13,46.55 U$1.3 64.38,46.6
DCC0  (via drill 0.5)
  Top 1: R2.1 R1.2 9.08,53.85 8.13,53.85 D1.C 7.68,56.5 6.93,57.25 v6.53,57.25 | D2.A 8.13,63.1 7.63,63.1 JP17.1
  Bottom 1: v6.53,57.25 6.53,62.05 JP17.1
DCC1
  Bottom 1: R4.1 R3.2 11.38,53.85 11.38,55.4 D3.C D4.A 12.48,60.45 12.48,62.9 12.68,63.1 JP18.1
DCC2  (via drill 0.5)
  Top 1: R6.1 R5.2 19.23,53.85 18.28,53.85 D5.C 17.83,56.5 17.68,56.65 v16.68,56.65 | D6.A 18.28,63.1 17.78,63.1 JP19.1
  Bottom 1: v16.68,56.65 16.68,61.8 17.73,62.85 17.73,63.1 JP19.1
DCC3
  Bottom 1: R8.1 R7.2 21.53,53.85 21.53,55.4 D7.C D8.A 22.63,60.45 22.63,62.9 22.83,63.1 JP20.1
DCC4  (via drill 0.5)
  Top 1: R10.1 R9.2 32.43,53.85 31.48,53.85 D9.C 31.03,56.5 30.83,56.7 v29.88,56.7 | D10.A 31.48,63.1 30.93,63.1 JP21.1
  Bottom 1: v29.88,56.7 29.88,62.05 30.93,63.1 JP21.1
DCC5
  Bottom 1: R12.1 R11.2 34.73,53.85 34.73,55.4 D11.C D12.A 35.98,60.4 35.98,63.1 JP22.1
DCC6  (via drill 0.5)
  Top 1: R14.1 R13.2 41.38,53.85 D13.C 41.83,56.5 42.53,57.2 v43.23,57.2 | D14.A 41.38,63.1 41.13,63.1 JP23.1
  Bottom 1: v43.23,57.2 43.23,61 41.13,63.1 JP23.1
DCC7
  Bottom 1: R16.1 R15.2 43.63,53.85 45.23,55.45 45.23,55.8 D15.C D16.A 45.73,60.45 45.73,62.7 46.13,63.1 JP24.1
DCC8  (via drill 0.5)
  Top 1: R18.1 R17.2 56.13,53.85 56.03,53.85 56.03,54.9 55.23,55.7 | 55.23,55.7 D17.C | v56.18,61.25 55.93,61.25 D18.A 55.88,58.8 v56.28,58.8 | 55.23,55.7 v56.28,56.75
  Bottom 1: v56.18,61.25 54.28,63.15 JP25.1 | v56.28,56.75 v56.28,58.8
DCC9
  Bottom 1: R20.1 R19.2 58.43,53.85 58.43,55.9 D19.C D20.A 59.03,60.45 59.03,62.8 59.33,63.1 JP26.1
DCC10  (via drill 0.5)
  Top 1: R22.1 R21.2 66.08,53.85 64.88,55.05 D21.C 64.43,56.5 63.73,57.2 v63.28,57.2 | D22.A 64.88,63.1 64.43,63.1 JP27.1
  Bottom 1: v63.28,57.2 63.28,62 JP27.1
DCC11
  Bottom 1: R24.1 67.88,51.5 R23.2 68.13,53.85 68.13,55.4 D23.C D24.A 69.23,60.45 69.23,62.85 69.48,63.1 JP28.1
DCC12  (via drill 0.5)
  Top 1: R26.1 R25.2 78.53,53.85 78.43,53.85 78.43,54.65 77.58,55.5 D25.C 77.13,56.5 76.43,57.2 v75.98,57.2 | D26.A 77.58,63.1 77.08,63.1 JP29.1
  Bottom 1: v75.98,57.2 75.98,62.05 77.03,63.1 JP29.1
DCC13
  Bottom 1: R28.1 R27.2 80.83,53.85 80.83,55.4 D27.C D28.A 81.93,60.45 81.93,62.9 82.13,63.1 JP30.1
DCC14  (via drill 0.5)
  Top 1: R30.1 R29.2 88.63,53.85 87.68,53.85 D29.C 87.23,56.5 86.48,57.25 v86.08,57.25 | D30.A 87.68,63.1 87.23,63.1 JP31.1
  Bottom 1: v86.08,57.25 86.08,61.95 87.23,63.1 JP31.1
DCC15
  Bottom 1: R32.1 R31.2 90.93,53.85 90.93,55.4 D31.C D32.A 92.03,60.45 92.03,62.85 JP32.1
DCC_OC_R  (via drill 0.5)
  Top 0.2: v49.48,15.9 49.83,15.9 49.83,18.35 U$2.47 | v46.53,10.75 44.58,8.8 44.58,7.1 42.08,7.1 35.78,13.4 30.58,13.4 30.28,13.7 OK1.6
  Bottom 0.2: v49.48,15.9 48.43,14.85 48.43,12.65 v46.53,10.75 | R110.1 30.23,14.15 30.23,13.75 OK1.6
DCC_OC_T  (via drill 0.5)
  Top 0.2: v70.73,39.75 71.03,40.05 71.68,40.05 72.83,41.2 72.83,42.55 74.18,42.55 77.98,46.35 v94.33,46.35 | v96.63,68.65 94.68,70.6 90.53,70.6 90.48,70.55 89.08,70.55 88.88,70.75 88.88,73.95 85.18,73.95 82.63,76.5 74.58,76.5 72.63,78.45 39.03,78.45 36.48,75.9 34.33,75.9 v32.88,74.45 | U$2.61 53.23,25.25 65.28,25.25 v65.63,25.6
  Bottom 0.2: v70.73,39.75 70.73,39.35 68.43,37.05 65.68,37.05 64.83,36.2 64.83,26.4 v65.63,25.6 | v94.33,46.35 96.48,48.5 96.48,68.5 v96.63,68.65 | v32.88,74.45 32.48,74.45 31.38,73.35 28.73,73.35 28.73,66.1 25.78,63.15 25.78,48.2 24.63,47.05 24.63,43.25 24.98,42.9 25.43,42.9 25.43,33.8 26.43,32.8 26.43,32.5 27.93,31 29.33,31 29.33,29.55 28.88,29.1 24.68,29.1 R111.1
DCCN  (via drill 0.5)
  Top 1: 11.03,56.25 R1.1 | 11.03,56.25 D1.A | R50.2 4.53,63 2.53,63 JP37.1 3.48,62.55 3.48,59.95 4.98,58.45 8.13,58.45 | 8.13,58.45 8.73,58.45 10.63,56.55 11.03,56.25 | 8.13,58.45 v8.13,58.35 | 43.73,53.85 45.48,55.6 | 43.73,53.85 R13.1 | 45.48,55.6 D13.A | v42.73,54.85 43.73,53.85 | 21.18,54.85 21.18,56.25 D5.A | 21.18,54.85 R5.1 | v20.33,54.85 21.18,54.85 | R9.1 34.38,56.25 D9.A 35.58,58.3 | 35.58,58.3 D10.C v39.68,60 | 18.28,58.45 20.83,58.45 D6.C 22.83,59.75 24.28,58.3 31.48,58.3 | 18.28,58.45 17.08,58.45 16.03,59.5 12.73,59.5 D2.C 11.78,59.85 v10.23,59.85 | 31.48,58.3 35.58,58.3 | 31.48,58.3 v31.48,58.35 | 18.28,58.45 v18.28,58.35 | 67.78,54.85 67.78,56.25 D21.A 69.43,56 v75.93,56 | 67.78,54.85 R21.1 | v66.48,60 D22.C | v66.93,54.85 67.78,54.85 | 58.08,54.85 58.08,56.25 D17.A | 58.08,54.85 R17.1 58.53,53.35 63.48,53.35 v64.18,54.05 | v57.23,54.85 58.08,54.85 | v53.08,60 D14.C | v56.38,60 D18.C | 80.48,54.85 80.48,56.25 D25.A 81.68,58.45 | 80.48,54.85 R25.1 | 81.68,58.45 D26.C | R29.1 90.58,56.25 D29.A 91.78,58.45 | 91.78,58.45 D30.C 92.23,60.25 94.83,62.85 97.73,62.85 98.13,63.25 JP39.1 | 81.68,58.45 87.68,58.45 | 87.68,58.45 91.78,58.45 | v79.63,54.85 80.48,54.85 | 87.68,58.45 v87.68,58.35 | v53.43,54.15 47.13,54.15 45.93,55.35 45.48,55.6
  Bottom 1: R3.1 8.13,54.7 D3.A v8.13,58.35 D4.C 8.58,59.85 v10.23,59.85 | R15.1 41.38,53.7 41.38,54.85 | 41.38,54.85 D15.A 41.63,56.7 42.03,57.1 42.03,59.35 D16.C v39.68,60 | 41.38,54.85 v42.73,54.85 | D8.C v18.28,58.35 D7.A 18.28,54.7 R7.1 19.58,54.1 v20.33,54.85 | R11.1 31.48,54.7 D11.A v31.48,58.35 D12.C | 64.88,54.7 R23.1 66.18,54.1 v66.93,54.85 | 64.88,54.7 D23.A D24.C v66.48,60 | 54.68,55.2 R19.1 56.48,54.1 v57.23,54.85 | 54.68,55.2 D19.A D20.C | D20.C v53.08,60 | D20.C v56.38,60 | v64.18,54.05 64.18,54.1 64.48,54.4 64.88,54.7 | R31.1 87.68,54.7 D31.A v87.68,58.35 D32.C | D27.A 77.58,54.7 R27.1 78.88,54.1 v79.63,54.85 | D27.A D28.C | v75.93,56 77.13,56 D27.A | v53.43,54.15 54.23,54.95 54.68,55.2
DCCP
  Top 1: JP39.2 98.13,65.85 92.78,65.85 JP32.2 92.28,65.7 87.68,65.7 JP31.2 87.23,65.7 82.63,65.7 JP30.2 82.13,65.7 77.08,65.7 JP29.2 76.58,65.65 69.98,65.65 JP28.2 69.48,65.7 64.88,65.7 JP27.2 64.38,65.7 59.78,65.7 JP26.2 59.33,65.7 54.28,65.7 JP25.2 53.78,65.6 46.68,65.6 JP24.2 46.13,65.7 41.58,65.7 JP23.2 41.08,65.7 36.48,65.7 JP22.2 35.98,65.7 30.93,65.7 JP21.2 30.48,65.7 23.33,65.7 JP20.2 22.78,65.6 18.28,65.6 JP19.2 17.73,65.7 12.73,65.7 JP18.2 12.18,65.6 7.68,65.6 JP17.2
  Bottom 1: JP37.2 2.53,65.6 R49.2 5.38,65.7 7.58,65.7 JP17.2
FTDI_RX  (via drill 0.5)
  Top 0.2: v38.23,17.25 39.33,18.35 U$2.26 | v51.03,12.8 50.83,13 48.73,13 48.18,12.45 40.08,12.45 v38.53,14 | v53.78,16.6 v55.48,18.3 | v56.93,17.5 57.13,17.7 64.78,17.7 v64.98,17.5
  Bottom 0.2: v51.03,12.8 53.78,15.55 v53.78,16.6 | v55.48,18.3 56.93,18.3 v56.93,17.5 | v64.98,17.5 64.88,17.4 64.88,15.8 63.93,14.85 63.93,14.2 JP33.4 | v38.23,17.25 38.23,14.3 v38.53,14 38.88,13.65
FTDI_TX  (via drill 0.5)
  Top 0.2: 39.83,18.35 U$2.27 39.83,18.25 39.83,17.15 v39.73,17.15 | JP33.3 66.43,14.15 65.48,13.2 63.53,13.2 62.78,13.95 43.09,13.95 43.03,14 42.88,14 v42.63,14.25
  Bottom 0.2: v42.63,14.25 v39.73,17.15
GND  (via drill 0.5, 0.6)
  Top 0.254: U$2.86 U$2.85 | 48.34,33.25 U$2.82 48.34,32.75 | U$2.86 U$2.87 | U$2.76 51.34,33.16 v50.93,32.75 | U$2.97 40.84,33.34 v41.43,32.75 | 42.34,32.75 U$2.94 | U$2.4 38.59,30.74 v39.08,30.25 | U$2.21 38.57,22.24 v39.08,22.75 | U$2.9 38.69,28.24 v39.08,27.85 | U$2.15 38.44,25.24 39.13,24.55 v39.13,24.05 | U$2.69 52.19,29.24 v51.93,29.5 | U$2.63 52.43,26.25 52.18,26.5 52.18,27.25 | 52.18,27.25 52.19,27.24 U$2.65 | v51.93,27.5 52.18,27.25 | U$2.57 52.44,23.24 v51.93,23.75 | U$2.54 52.17,21.74 v51.93,21.5 | U$2.86 46.34,32.84 v46.43,32.75 | U$2.33 42.84,19.34 v42.43,19.75 | U$2.42 47.34,19.04 R85.1 46.28,19.6 45.84,19.16 U$2.39 | U$2.50 51.34,19.19 v50.78,19.75 | U$2.45 48.84,19.59 v48.68,19.75 | U$3.10 53.44,43.65 U$3.9 54.93,43.26 54.93,42.9 C55.2 54.93,42.25 53.99,41.31 U$3.6 52.43,41.31 52.43,39.36 U$3.3 | U$3.30 44.79,43.26 C54.2 | U$3.35 44.77,40.01 C56.2
  Top 0.406: U$3.20 46.98,49.76 50.42,49.76 | U$4.4 68.43,41.66 v68.43,42 | v52.23,39.2 52.33,39.3 52.43,39.36 | 50.42,49.76 U$3.19 | 50.42,49.76 50.38,49.8
  Top 1: v17.98,40.5 v20.68,40.5 v24.33,40.5 24.78,40.75 24.83,40.8 v34.48,40.8 v37.73,40.8 38.28,40.8 v40.98,43.5 | 50.38,49.8 50.38,43.65 53.44,43.65 | v46.98,49.6 46.98,49.76 | v53.68,36.65 53.43,36.65 53.43,35.05 51.38,33 51.33,33 v50.93,32.75 | JP33.5 66.48,11.65 68.68,13.85 v70.98,13.85 76.48,13.85 X4.S1 | JTAG1.20 73.78,43.55 72.38,44.95 70.53,44.95 68.53,42.95 68.43,42.95 v68.43,42 | 68.48,42.9 v59.43,42.9 54.93,42.9 | C4.2 25.68,77.4 25.63,77.45 22.88,77.45 JP4.1 | JP2.1 12.73,77.5 17.73,77.5 JP3.1 | C12.2 72.03,77.55 71.98,77.5 69.53,77.5 JP12.1 | JP8.1 46.18,77.5 54.23,77.5 JP9.1 | 86.78,41.5 87.73,41.5 S6.3 | 86.78,41.5 85.83,41.5 S3.4 | R102.2 84.03,44 86.73,44 S1.3 | S1.3 87.28,44 S1.4 93.78,43.85 93.98,43.65 96.43,43.65 98.33,41.75 S4.4 98.83,41.5 98.83,35.5 S4.3 98.78,34.95 96.63,32.8 | 86.78,41.5 86.78,43.5 S1.3 | 86.78,35 87.73,35 S6.4 | 86.78,35 85.83,35 S3.3 | 86.78,35 86.78,32.55 S2.4 87.28,32.55 93.28,32.55 S2.3 93.73,32.8 96.63,32.8 | v33.53,11.4 33.33,11.2 30.28,11.2 OK1.5 | X4.S2 92.03,13.85 92.58,13.3 96.68,13.3 98.58,15.2 S5.4 99.08,15.45 99.03,15.45 99.03,17.95 C32.2 98.78,18.4 98.78,20.65 C33.2 98.83,21.2 98.83,22.95 C31.2 98.78,23.45 98.78,25.6 C30.2 98.53,26.05 98.53,30.7 96.88,32.35 96.63,32.8 | C67.2 C66.2 C65.2 C64.2 C63.2 31.63,6.85 33.53,6.85 C37.2 | C36.2 34.23,6.5 C37.2 | 33.68,1.25 33.68,3.35 U$1.26 33.78,3.9 C37.2 | C39.2 C38.2 47.03,8.35 47.03,9.1 v52.53,9.1 54.03,9.1 v55.68,7.45 | v55.68,5.75 C62.2 51.03,3.4 51.43,3.4 U$1.33 51.43,2.9 51.43,1.25 | v10.43,15.35 10.43,20.55 11.83,21.95 X3.3
  Top 1.016: 12.68,1.25 14.68,1.25 | IC3.GND 10.79,3.14 | v41.43,32.75 42.34,32.75 | v46.43,32.75 48.34,32.75 | 44.28,41.75 C54.2 | 44.28,41.75 C56.2 | v44.18,41.75 44.28,41.75
  Top 1.27: IC3.GND 10.79,6.67 C25.2 2.47,6.67 JP40.1 | v75.68,4.25 72.68,1.25 51.43,1.25 33.68,1.25 12.68,1.25 10.79,1.25 10.79,3.14
  Bottom 0.254: v50.93,32.75 50.43,32.75 | v51.93,29.5 51.68,29.5 51.43,29.25 | v51.93,23.75 51.93,23.89 51.68,24.14 | R85.1 46.33,19.6 46.18,19.75
  Bottom 0.406: v68.43,42 67.28,42 C69.2
  Bottom 1: v17.98,40.5 Q5.E | v20.68,40.5 21.23,41.05 Q4.E | Q3.E 24.33,41.75 v24.33,40.5 | 43.43,46.1 43.43,46.3 44.43,47.3 44.93,47.3 44.93,47.55 v46.98,49.6 | 43.43,46.1 43.43,45.3 43.63,45.1 43.63,42.35 43.73,42.25 43.93,41.75 | v40.98,43.5 41.33,43.85 41.33,44.45 42.98,46.1 43.43,46.1 | v53.68,36.65 53.43,36.9 53.43,38 v52.23,39.2 | C35.2 78.83,19 79.78,18.05 79.78,17.2 X4.8 79.43,16.85 76.53,13.95 76.53,13.9 X4.S1 | JTAG1.20 73.83,41.5 JTAG1.18 73.78,41 73.78,39 JTAG1.16 73.83,38.45 73.83,36.45 JTAG1.14 73.83,35.9 73.83,33.9 JTAG1.12 73.83,33.35 73.83,31.3 JTAG1.10 73.83,28.8 JTAG1.8 73.78,28.3 73.78,26.3 JTAG1.6 73.83,25.75 73.83,23.25 JTAG1.4 74.18,22.85 75.18,21.85 75.18,19.1 78.28,19.1 C35.2 | C8.2 48.68,77.55 46.18,77.55 46.18,77.5 JP8.1 45.68,77.55 44.08,77.55 C7.2 43.63,77.55 41.13,77.55 41.13,77.5 JP7.1 40.63,77.6 39.03,77.6 C6.2 38.53,77.6 36.48,77.6 JP6.1 35.98,77.5 35.98,77.55 33.48,77.55 C5.2 32.98,77.5 30.93,77.5 JP5.1 30.48,77.75 27.43,77.75 C23.- 26.98,78 23.08,78 JP4.1 22.83,77.5 22.83,77.55 20.33,77.55 C3.2 19.83,77.5 17.78,77.5 JP3.1 | C2.2 15.23,77.55 13.18,77.55 JP2.1 12.68,77.5 12.68,77.55 10.18,77.55 C1.2 9.68,77.5 7.63,77.5 JP1.1 | JP9.1 54.28,77.5 56.28,77.5 56.28,77.55 C9.2 56.83,77.55 59.33,77.55 JP10.1 59.78,77.6 61.83,77.6 C10.2 62.38,77.5 64.38,77.5 JP11.1 64.88,77.65 66.43,77.65 C11.2 66.98,77.55 69.48,77.55 69.48,77.5 JP12.1 69.73,78 69.73,78.2 73.18,78.2 C24.- 73.68,78.05 76.68,78.05 76.68,77.85 JP13.1 77.08,77.5 79.13,77.5 C13.2 79.63,77.55 82.13,77.55 82.13,77.5 JP14.1 82.63,77.6 84.68,77.6 C14.2 85.18,77.5 87.23,77.5 JP15.1 87.68,77.5 89.28,77.5 C15.2 89.78,77.55 92.28,77.55 92.28,77.5 JP16.1 92.78,77.6 94.83,77.6 C16.2 95.33,77.45 95.98,76.8 95.98,76.75 96.03,76.7 96.03,76.65 96.08,76.6 96.08,75.75 98.13,73.7 JP38.2 97.73,73.4 95.48,71.15 95.48,53.45 91.13,49.1 91.13,47.95 93.23,45.85 93.23,44.05 S1.4
  Bottom 1: C68.1 33.53,13.75 v33.53,11.4 | OK2.2 22.63,23.95 22.73,23.85 22.73,22.5 26.98,18.25 26.98,13.2 28.28,11.9 30.23,11.9 OK1.5 30.43,10.7 31.13,10 31.13,5.9 33.63,3.4 U$1.26 | X3.3 11.88,22 11.88,24.5 X3.5 11.58,24.95 9.73,26.8 9.73,38.3 11.43,40 X1.3 11.88,39.5 11.88,42 X1.5 | C34.2 89.88,13.9 91.98,13.9 X4.S2 | C58.2 99.08,15.6 99.08,15.45 S5.4 99.08,14.95 99.08,9.55 S5.3 | v55.68,5.75 v55.68,7.45 | v10.43,15.35 11.43,14.35 11.43,10.05 C18.- | C35.2 79.23,19.25 79.28,19.3 79.63,19.3 79.63,18.95 80.88,17.7 80.88,14.5 83.48,11.9 83.48,8.5 IC4.2
  Bottom 1.016: 45.68,32.75 45.68,34 C46.2 C40.2 44.03,32.75 | 50.53,32.75 C41.2 | 45.68,32.75 v46.43,32.75 50.43,32.75 50.53,32.75 | 50.53,32.75 v50.93,32.75 51.18,32.75 51.93,32 | 39.08,32.75 C53.2 | 44.93,32.75 44.03,32.75 | 45.68,32.75 44.93,32.75 | 39.08,32.75 v41.43,32.75 44.03,32.75 | 44.93,32.75 44.93,33.75 | C52.2 51.93,29.1 51.93,29.25 | 51.93,32 v51.93,29.5 | v51.93,29.5 51.93,29.25 | C51.2 52.03,32.1 51.93,32 | 51.93,24.15 v51.93,23.75 v51.93,21.5 51.93,20.9 | 51.93,20.9 C50.2 | 50.18,19.75 C47.2 | 50.18,19.75 v48.68,19.75 46.18,19.75 43.38,19.75 | 43.38,19.75 C42.2 | 51.93,20.9 v50.78,19.75 50.18,19.75 | C44.2 C43.2 37.68,29.5 39.08,29.5 | 39.08,29.5 v39.08,30.25 39.08,32.75 | C21.2 39.08,24.15 39.08,24 | 51.93,29.25 51.43,29.25 C48.- C22.- 51.68,24.14 51.93,24.14 51.93,24.15 | C49.2 38.33,21.15 39.08,21.9 v39.08,22.75 39.08,24 | C45.2 40.33,19.15 40.93,19.75 v42.43,19.75 43.38,19.75 | 39.08,24 v39.13,24.05 40.43,25.35 40.43,26.5 v39.08,27.85 39.08,29.5 | 51.93,24.15 C29.2 | v51.93,29.5 v51.93,27.5 | 43.93,41.75 v44.18,41.75 | 67.28,40.85 C57.2 | C69.2 67.28,40.85 | 67.28,40.85 C70.2
  Bottom 1.27: IC3.GND 10.79,6.33 | 10.79,6.33 C26.2 | 10.79,6.33 10.79,8.56 C18.- 14.65,9.49 C17.- | 83.66,1.9 IC4.4 IC4.2 | 78.93,1.9 C19.- 75.68,2.02 v75.68,4.25 | 78.93,1.9 83.66,1.9 | C27.2 78.94,1.91 78.93,1.9 | 91.51,1.9 C20.- | 88.42,1.9 91.51,1.9 | 88.42,1.9 C28.2 | 83.66,1.9 88.42,1.9 | S5.3 99.08,7.4 93.58,1.9 91.51,1.9
  other vias: 46.78,19.6
  pour Bottom: 0.93,0.5 99.93,0.5 99.93,79.5 0.93,79.5
I2C_SCL  (via drill 0.5)
  Top 0.2: v65.08,14.9 64.83,15.15 63.48,15.15 62.68,14.35 43.56,14.35 43.48,14.4 43.38,14.4 43.38,16.35 43.33,16.4 43.33,18.35 U$2.34
  Bottom 0.2: v65.08,14.9 66.43,16.25 66.43,16.7 JP33.1
I2C_SDA  (via drill 0.5)
  Top 0.2: v54.88,15.5 56.08,16.7 63.88,16.7 JP33.2 | U$2.35 43.88,18.35 43.88,15.56 v44.17,15.27
  Bottom 0.2: v54.88,15.5 54.88,5.95 47.48,5.95 45.78,7.65 45.78,13.95 44.46,15.27 v44.17,15.27
KEY_RX
  Top 0.2: U$2.75 53.23,32.2 58.98,32.2 59.18,32 D36.3 79.33,32.05 79.33,33.35 77.93,34.75 | 79.53,36.75 D35.3 79.53,36.65 79.68,36.5 | 77.93,34.75 72.83,34.75 72.83,36.3 73.43,36.9 74.78,36.9 74.78,39.15 76.23,40.6 79.13,40.6 D34.3 79.28,42.45 R102.1 | 77.93,34.75 79.68,36.5 | 79.68,36.5 79.88,36.7
N$1  (via drill 0.5)
  Top 0.2: v46.83,16.6 46.83,18.35 U$2.41
  Bottom 0.2: v46.83,16.6 46.73,16.7 46.73,17.7 R85.2
  Bottom 0.254: R85.2 46.68,17.8
N$2
  Top 0.254: U$3.8 U$3.7
N$3  (via drill 0.5)
  Top 0.2: v19.23,34.35 19.58,34 35.73,34 U$2.1 | v17.73,32.85 17.38,33.2 8.88,33.2 7.73,34.35 7.73,35.05 8.23,35.55 8.23,40.3 v10.58,42.65
  Bottom 0.2: v17.73,32.85 v19.23,34.35 | v10.58,42.65 10.83,42.9 10.83,48.8 R86.2
N$4  (via drill 0.5)
  Top 0.2: v8.38,71.05 8.38,69.85 LED1.A
  Bottom 0.2: v8.38,71.05 8.43,71 8.43,69.85 R33.1
N$5
  Top 0.2: 43.83,5.75 C60.2 | C59.2 43.83,5.75 | 43.83,5.75 U$1.30
N$6  (via drill 0.5)
  Top 0.2: v13.48,71.05 13.48,69.85 LED3.A
  Bottom 0.2: v13.48,71.05 13.53,71 R34.1
N$7  (via drill 0.5)
  Top 0.2: v9.48,40.45 11.48,38.45 12.38,38.45 12.93,37.9 12.93,33.6 33.98,33.6 35.83,31.75 U$2.2 | v7.43,48.45 7.98,49 R87.2
  Bottom 0.2: v9.48,40.45 8.63,41.3 8.63,45.5 7.48,46.65 7.48,48.4 v7.43,48.45
N$8  (via drill 0.5)
  Top 0.2: v18.53,71.05 LED5.A
  Bottom 0.2: v18.53,71.05 18.58,71 18.58,69.85 R35.1
N$9  (via drill 0.5)
  Top 0.2: v33.63,32.85 33.83,32.85 36.43,30.25 U$2.5 | v32.03,48.85 v22.58,48.85
  Bottom 0.2: v33.63,32.85 32.03,34.45 v32.03,48.85 | v22.58,48.85 21.28,48.85 R88.2
N$10  (via drill 0.5)
  Top 0.2: v25.68,32.45 26.43,31.7 34.38,31.7 36.33,29.75 U$2.6 | v22.78,38.05 21.83,39 v15.83,39 | v17.63,47.6 19.03,49 R89.2
  Bottom 0.2: v25.68,32.45 22.78,35.35 v22.78,38.05 | v15.83,39 15.83,45.8 v17.63,47.6
N$11
  Top 0.2: LED33.A 98.18,48 R117.1
N$12
  Top 0.2: R65.2 6.08,72.35 7.58,72.35 JP1.3
N$13  (via drill 0.5)
  Top 0.2: v75.73,41.7 D34.1 79.83,44.45 79.83,45.8 85.33,45.8 v85.53,45.6 | S1.2 93.28,48.55 86.78,48.55 S1.1
  Bottom 0.2: v75.73,41.7 D34.1 R96.1 | v85.53,45.6 86.73,46.8 86.73,48.5 S1.1
N$14
  Top 0.2: D34.2 77.23,39.95 80.13,39.95 81.23,41.05 81.23,41.5 S3.2
  Bottom 0.2: R97.1 77.83,38.75 77.83,38.6 77.98,38.45 81.23,38.45 | 81.23,38.45 81.23,41.5 S3.2 | S3.1 81.28,38.4 81.23,38.45
N$15  (via drill 0.5)
  Top 0.2: v75.73,37.45 D35.1 79.18,39.55 90.33,39.55 S6.1
  Bottom 0.2: v75.73,37.45 D35.1 R98.1 | S6.2 92.33,35 92.33,41.5 S6.1
N$16
  Top 0.2: R66.2 10.18,71.35 11.18,72.35 12.68,72.35 JP2.3
N$17
  Top 0.2: C59.1 41.58,3.4 41.33,3.4 U$1.29
N$18  (via drill 0.5)
  Top 0.2: v75.33,35.95 76.68,35.95 D35.2 77.03,35.7 78.28,36.95 78.28,37.3 94.23,37.3 | 94.23,35.2 94.23,35 S4.1 94.23,35 94.23,36.05 94.23,37.3 | S4.2 94.23,41.5 94.23,37.3
  Bottom 0.2: v75.33,35.95 75.83,35.95 76.78,35 R99.1
N$19  (via drill 0.5)
  Top 0.2: v75.73,32.95 D36.1 | v81.53,28.15 81.68,28 86.73,28 S2.2 86.88,28 S2.1
  Bottom 0.2: v75.73,32.95 D36.1 R100.1 77.83,32 77.83,31.85 v81.53,28.15
N$20
  Top 0.2: R67.2 16.23,72.35 17.73,72.35 JP3.3
N$21
  Top 0.2: C61.1 36.23,4.4 36.23,3.4 U$1.27
N$22  (via drill 0.5)
  Top 0.2: LED7.A v24.88,69.85
  Bottom 0.2: v24.88,69.85 R36.1
N$23
  Top 0.2: C61.2 39.78,3.4 38.78,3.4 U$1.28
N$24
  Top 0.2: C60.1 46.53,3.4 U$1.31
N$25
  Top 0.2: C62.1 49.33,3.4 48.93,3.4 U$1.32
N$26
  Top 0.2: R68.2 20.33,71.35 21.33,72.35 22.83,72.35 JP4.3
N$28  (via drill 0.5)
  Top 0.2: LED9.A v31.68,71.05
  Bottom 0.2: v31.68,71.05 31.78,70.95 R37.1
N$29
  Top 0.2: C63.1 31.18,3.4 U$1.25
N$30
  Top 0.2: C64.1 28.68,3.4 28.63,3.4 U$1.24
N$31
  Top 0.2: C65.1 26.18,3.4 26.08,3.4 U$1.23
N$32
  Top 0.2: R69.2 28.43,71.35 29.43,72.35 30.93,72.35 JP5.3
N$33
  Top 0.2: C66.1 23.68,3.4 23.53,3.4 U$1.22
N$34  (via drill 0.5)
  Top 0.2: v36.78,71.05 36.78,69.85 LED11.A
  Bottom 0.2: v36.78,71.05 36.83,71 36.83,69.85 R38.1
N$35
  Top 0.2: C67.1 21.18,3.4 U$1.21
N$36
  Top 0.2: R70.2 34.48,72.35 35.98,72.35 JP6.3
N$37  (via drill 0.5)
  Top 0.2: v41.88,71.05 41.88,69.85 LED13.A
  Bottom 0.2: v41.88,71.05 41.93,71 R39.1
N$38  (via drill 0.5)
  Top 0.2: v51.68,15.9 50.93,16.65 50.88,16.65 50.88,18.35 U$2.49 | C38.1 v53.58,7.9
  Bottom 0.2: v51.68,15.9 50.28,14.5 50.28,7.25 Q2.1 50.33,7.9 v53.58,7.9
N$39
  Top 0.2: R71.2 38.58,71.35 39.58,72.35 41.08,72.35 JP7.3
N$40  (via drill 0.5)
  Top 0.2: LED15.A v48.18,69.85
  Bottom 0.2: v48.18,69.85 R40.1
N$41  (via drill 0.5)
  Top 0.2: v50.58,15.9 50.38,15.9 50.38,18.35 U$2.48 | C39.1 42.33,7.9 42.33,10.75 v42.23,10.75 42.38,10.8 43.53,11.95 48.78,11.95 v49.08,12.25
  Bottom 0.2: v50.58,15.9 49.18,14.5 49.18,12.8 49.08,12.7 v49.08,12.25 | v42.23,10.75 42.23,8.85 40.63,7.25 Q2.2
N$42
  Top 0.2: R72.2 44.63,72.35 46.13,72.35 JP8.3
N$43  (via drill 0.5)
  Top 0.2: v55.08,71.05 55.03,71.05 55.03,69.85 LED17.A
  Bottom 0.2: v55.08,71.05 55.08,69.85 R41.1
N$44  (via drill 0.5)
  Top 0.2: v26.83,43.25 26.23,43.85 R104.1
  Bottom 0.2: Q3.B 26.83,42.35 v26.83,43.25
N$45
  Top 0.2: R73.2 51.73,71.35 52.73,72.35 54.23,72.35 JP9.3
N$46  (via drill 0.5)
  Top 0.2: LED19.A v60.08,71.05
  Bottom 0.2: v60.08,71.05 60.18,70.95 R42.1
N$47  (via drill 0.5)
  Top 0.2: v23.58,43.25 22.98,43.85 R105.1
  Bottom 0.2: Q4.B 23.58,42.35 v23.58,43.25
N$48
  Top 0.2: R74.2 56.83,71.35 57.83,72.35 59.33,72.35 JP10.3
N$49  (via drill 0.5)
  Top 0.2: v65.18,71.05 65.18,69.85 LED21.A
  Bottom 0.2: v65.18,71.05 65.23,71 65.23,69.85 R43.1
N$50  (via drill 0.5)
  Top 0.2: v20.33,43.25 19.73,43.85 R106.1
  Bottom 0.2: Q5.B 20.33,42.35 v20.33,43.25
N$51
  Top 0.2: R75.2 62.88,72.35 64.38,72.35 JP11.3
N$52  (via drill 0.5)
  Top 0.2: LED23.A v71.53,69.85
  Bottom 0.2: v71.53,69.85 R44.1
N$53  (via drill 0.5)
  Top 0.2: v4.93,61 R50.1 | v1.75,20.14 1.59,20.14 1.02,20.71 1.02,29.72 v1.91,30.61 | v6.42,20.57 6.71,20.28 v8.19,20.28
  Bottom 0.2: 22.58,13.9 22.58,13.75 OK1.3 | R115.2 22.68,13.1 22.68,13.65 OK1.3 | OK1.3 22.05,14.3 D41.1 16.04,14.3 12.38,17.96 10.51,17.96 v8.19,20.28 | v4.93,61 5.18,60.75 5.18,60.35 1.91,57.08 v1.91,30.61 | v1.75,20.14 5.76,20.14 | 5.76,20.14 5.77,20.15 | v6.42,20.57 5.99,20.14 5.76,20.14
N$54
  Top 0.2: R76.2 66.98,71.35 67.98,72.35 69.48,72.35 JP12.3
N$55  (via drill 0.5)
  Top 0.2: v77.83,71.05 LED25.A
  Bottom 0.2: v77.83,71.05 77.88,71 77.88,69.85 R45.1
N$56  (via drill 0.5)
  Top 0.2: v17.78,23.65 17.18,24.25 13.98,24.25 13.23,23.5 11.62,23.5 9.32,21.2 9.32,17.33 v8.92,16.93
  Bottom 0.2: R109.2 R114.2 19.13,22.3 v17.78,23.65 | R49.1 4.18,63.15 4.18,60.75 1.13,57.7 1.13,38.66 0.79,38.32 0.79,19.44 4.6,15.63 6.82,15.63 8.12,16.93 v8.92,16.93
N$57
  Top 0.2: R77.2 75.53,72.35 77.03,72.35 JP13.3
N$58  (via drill 0.5)
  Top 0.2: v82.93,71.05 82.93,69.85 LED27.A
  Bottom 0.2: v82.93,71.05 82.98,71 82.98,69.85 R46.1
N$59
  Bottom 0.2: Q3.C 26.03,44.7 26.03,46.55 U$1.18
N$60
  Top 0.2: R78.2 79.63,71.35 80.63,72.35 82.13,72.35 JP14.3
N$61  (via drill 0.5)
  Top 0.2: LED29.A v87.98,71.05
  Bottom 0.2: v87.98,71.05 88.08,70.95 R47.1
N$62
  Bottom 0.2: Q4.C 23.48,45.4 23.48,46.55 U$1.19
N$63
  Top 0.2: R79.2 84.73,71.35 85.73,72.35 87.23,72.35 JP15.3
N$64  (via drill 0.5)
  Top 0.2: LED31.A v94.33,69.85
  Bottom 0.2: v94.33,69.85 R48.1
N$65  (via drill 0.5)
  Top 0.2: v19.08,45.45 20.18,46.55 20.93,46.55 U$1.20
  Bottom 0.2: Q5.C 19.08,44.25 v19.08,45.45
N$66
  Top 0.2: R80.2 90.78,72.35 92.28,72.35 JP16.3
N$68  (via drill 0.5)
  Top 0.406: U$4.5 64.68,41.66 v64.68,41.75
  Bottom 0.406: v64.68,41.75 C69.1
N$69  (via drill 0.5)
  Top 0.2: U$3.4 53.48,40 53.98,40 54.18,39.8 57.58,39.8 58.18,40.4 62.88,40.4 U$4.6
  Top 0.406: U$4.6 64.68,40.38 v64.68,40.25
  Bottom 0.406: v64.68,40.25 65.58,40.25 C70.1
N$83
  Bottom 0.2: R107.1 81.33,26.45 81.33,24.6 X4.C1
N$84
  Bottom 0.2: R108.1 89.73,26.45 89.73,24.6 X4.C2
N$85
  Bottom 0.2: 22.58,16.3 OK1.2
  Bottom 0.406: R109.1 19.18,15.85 D41.3 20.83,16.3 22.58,16.3
N$86
  Bottom 0.2: Q6.B 28.43,28.2 R112.2 28.48,26.55 30.23,26.55 OK2.4
N$87
  Bottom 0.2: R111.2 22.63,26.4 22.63,26.5 OK2.1
N$88  (via drill 0.5)
  Top 0.2: OK2.3 30.23,24 29.33,24.9 21.73,24.9 19.83,26.8 13.98,26.8 13.23,26.05 5.63,26.05 3.67,28.01 v3.67,28.24
  Bottom 0.2: D40.1 3.43,22.7 3.43,22.95 3.33,23.05 3.33,24.35 4.03,25.05 D39.1 3.98,25.1 JDCCO.1 2.18,27.5 2.92,28.24 v3.67,28.24 | Q6.C 32.38,27.4 32.38,26.1 30.28,24 OK2.3 30.18,24.05 30.18,24.4 R112.1
N$89
  Bottom 0.2: Q6.E 26.28,30.2 R113.1
N$90  (via drill 0.5)
  Top 0.2: v23.28,30.95 22.18,29.85 8.53,29.85 v5.83,27.15
  Bottom 0.2: 5.33,23.7 D40.2 | 5.33,23.7 5.33,25.95 4.98,26.3 | 4.98,26.3 D39.2 | JDCCO.2 3.03,22.55 3.03,21.45 3.48,21 5.33,21 5.33,23.7 | R113.2 23.73,30.5 v23.28,30.95 | 4.98,26.3 v5.83,27.15
N$91
  Bottom 0.2: R115.1 24.43,12.1 21.73,12.1 20.98,12.85 16.16,12.85 12.26,16.75 10.64,16.75 8.8,18.59 7.95,18.59 7.36,19.18 7.36,21.01 6.53,21.84 D40.3
N$92  (via drill 0.5)
  Top 0.2: v7.38,24.85 8.08,25.55 13.18,25.55 13.98,24.75 v17.78,24.75
  Bottom 0.2: D39.3 7.38,25.15 v7.38,24.85 | v17.78,24.75 18.88,24.75 18.88,24.4 R114.1
PHY_LED0  (via drill 0.5)
  Top 0.2: v76.83,24.25 53.23,24.25 U$2.59
  Bottom 0.2: v76.83,24.25 R107.2
PHY_LED1  (via drill 0.5)
  Top 0.2: v84.43,27.25 78.73,27.25 76.18,24.7 53.23,24.7 U$2.60
  Bottom 0.2: R108.2 89.63,28.35 88.08,26.8 84.88,26.8 v84.43,27.25
RST_N  (via drill 0.5)
  Top 0.2: v56.03,26.7 53.23,26.7 U$2.64 | v60.48,4.7 60.68,4.9 65.18,4.9 65.78,4.3 | 65.78,4.3 U$1.39 | S5.1 94.53,8.9 91.58,5.95 67.43,5.95 65.78,4.3
  Bottom 0.2: R101.1 96.68,12.1 C58.1 95.18,15.4 94.58,15.4 S5.2 | v60.48,4.7 60.48,19.45 56.03,23.9 v56.03,26.7
  Bottom 0.254: 96.68,12 R101.1 96.53,8.93 S5.1
RXIN  (via drill 0.5)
